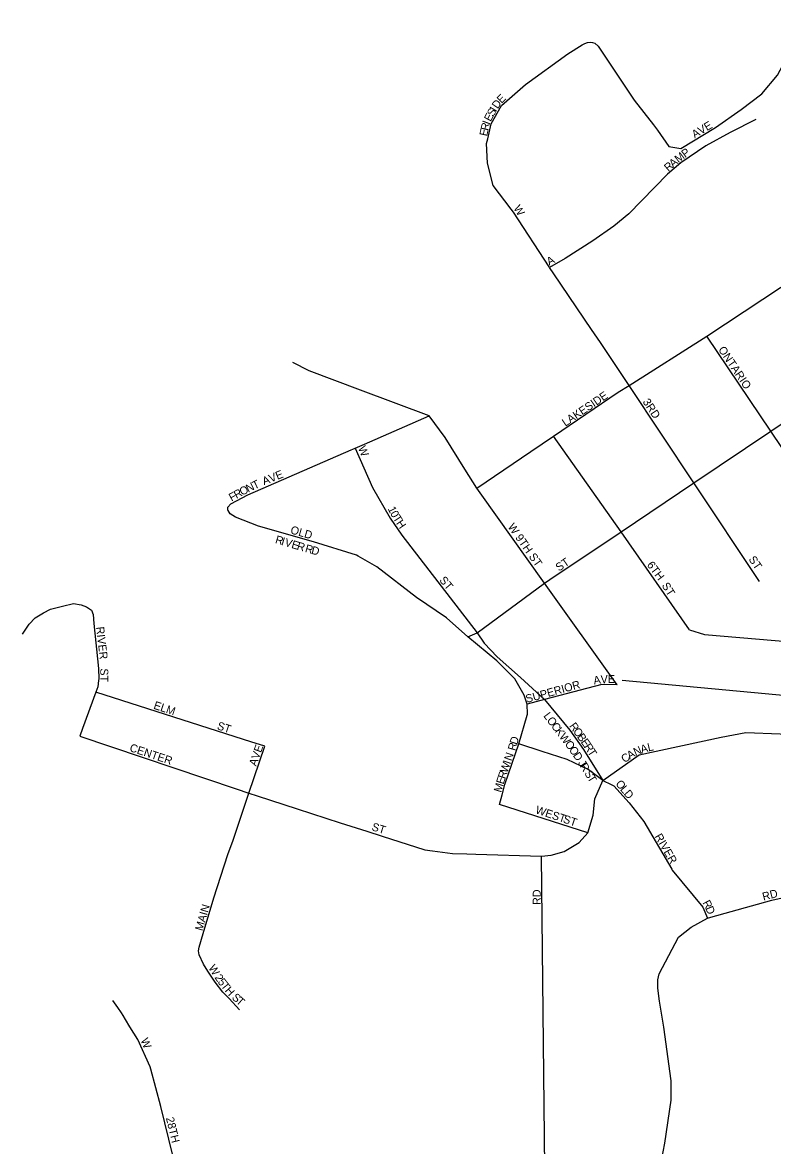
# Model space of a CAD drawing. Extents: x 0 to 96.2, y -27.5 to 31.3.
# Drawn here: x 3.858 to 4.744, y 18.275 to 19.6 of the extents above; entities that cross this region are included whole.
import ezdxf

# ---------------------------------------------------------------- set-up
doc = ezdxf.new("R2010")
doc.units = 0
doc.layers.add('TB_PP_20x10_GRID', color=7, linetype='Continuous')
doc.layers.add('TB_PP_30x10', color=7, linetype='Continuous')

msp = doc.modelspace()

# ---------------------------------------------------------------- linework, layer by layer
at = {"layer": 'TB_PP_20x10_GRID'}
for points in [[(4.608, 19.4727), (4.6213, 19.4537), (4.6356, 19.4511), (4.6765, 19.4758), (4.7067, 19.497), (4.7309, 19.5157), (4.7496, 19.5375), (4.7593, 19.5562), (4.7701, 19.5754), (4.784, 19.5861), (4.8006, 19.5998)], [(4.4076, 19.4626), (4.4118, 19.4803), (4.424, 19.5019), (4.4522, 19.5268), (4.5021, 19.5628), (4.5192, 19.5734), (4.5222, 19.5749), (4.5254, 19.5761), (4.5287, 19.5764), (4.5312, 19.5762), (4.5341, 19.5752), (4.5379, 19.572), (4.5802, 19.508), (4.6034, 19.4791), (4.608, 19.4727)], [(4.5743, 19.1717), (4.6662, 19.2297), (4.8411, 19.3455), (4.9286, 19.4096), (5.0545, 19.4913), (5.1255, 19.5402), (5.1289, 19.5424)], [(4.724, 19.4852), (4.6935, 19.4702), (4.6649, 19.4544), (4.6354, 19.4341), (4.6196, 19.4208), (4.574, 19.3741), (4.5563, 19.3596), (4.5317, 19.3424), (4.499, 19.3215), (4.4806, 19.3107)], [(4.4353, 19.3794), (4.414, 19.4077), (4.4074, 19.4337), (4.4063, 19.457), (4.4076, 19.4626)], [(4.4799, 19.3116), (4.4378, 19.3761), (4.4353, 19.3794)], [(4.5405, 19.2224), (4.5301, 19.2376), (4.4856, 19.3032), (4.4806, 19.3107), (4.4799, 19.3116)], [(4.4808, 18.9427), (4.565, 18.9991), (4.6509, 19.0567), (4.7418, 19.1176), (4.9176, 19.2354), (5.0055, 19.2943)], [(4.5743, 19.1717), (4.5405, 19.2224)], [(4.7433, 19.1154), (4.7418, 19.1176), (4.6662, 19.2297)], [(4.2576, 19.1662), (4.1968, 19.189), (4.1776, 19.1986)], [(4.4852, 19.1119), (4.5617, 19.1638), (4.5743, 19.1717)], [(4.7283, 18.9404), (4.6509, 19.0567), (4.5743, 19.1717)], [(4.3385, 19.136), (4.2576, 19.1662)], [(4.2483, 19.0965), (4.251, 19.0977), (4.2623, 19.1026), (4.3385, 19.136)], [(4.3987, 19.0449), (4.3948, 19.0505), (4.3806, 19.0729), (4.3572, 19.1101), (4.3385, 19.136)], [(4.8205, 19.001), (4.7894, 19.0472), (4.7433, 19.1154)], [(4.4586, 19.0938), (4.485, 19.1118), (4.4852, 19.1119)], [(4.6455, 18.8834), (4.565, 18.9991), (4.485, 19.1118)], [(4.1013, 19.024), (4.1009, 19.0246), (4.1009, 19.0264), (4.1009, 19.0283), (4.1045, 19.0319), (4.1244, 19.0427), (4.2465, 19.0957), (4.2483, 19.0965)], [(4.251, 19.0977), (4.2715, 19.0513), (4.2925, 19.0153), (4.3063, 18.9952), (4.3952, 18.8799)], [(4.3948, 19.0505), (4.4586, 19.0938)], [(4.5602, 18.8186), (4.4747, 18.9386), (4.3987, 19.0449)], [(4.3839, 18.8752), (4.3591, 18.8977), (4.3235, 18.9215), (4.2765, 18.9579), (4.2548, 18.9702), (4.2528, 18.9714), (4.2021, 18.9873), (4.1372, 19.0057), (4.1097, 19.0165), (4.1035, 19.0204), (4.1013, 19.024)], [(4.3839, 18.8752), (4.3952, 18.8799), (4.4747, 18.9386), (4.4808, 18.9427)], [(3.8584, 18.8784), (3.8663, 18.8901), (3.8736, 18.8974), (3.8832, 18.9033), (3.8914, 18.9079), (3.9056, 18.9113), (3.9058, 18.9114)], [(3.9058, 18.9114), (3.9188, 18.9146), (3.9278, 18.913), (3.9342, 18.9106), (3.9398, 18.9066), (3.942, 18.9016), (3.9426, 18.8907), (3.9481, 18.838), (3.9484, 18.8256), (3.9483, 18.8236)], [(4.3952, 18.8799), (4.4033, 18.8677), (4.4187, 18.8514), (4.4462, 18.8272), (4.4746, 18.8012), (4.5043, 18.765), (4.5207, 18.7424), (4.5436, 18.7057)], [(4.6455, 18.8834), (4.6634, 18.8781), (4.8069, 18.8658)], [(4.4542, 18.7829), (4.4546, 18.7841), (4.454, 18.7957), (4.4506, 18.8064), (4.4394, 18.8256), (4.4182, 18.8467), (4.3839, 18.8752)], [(3.9483, 18.8236), (3.9475, 18.816), (3.945, 18.8098), (3.9293, 18.7669)], [(4.5662, 18.8241), (4.9798, 18.7855), (5.0011, 18.7941)], [(4.5602, 18.8186), (4.5421, 18.819), (4.4746, 18.8012), (4.454, 18.7957)], [(4.1432, 18.7465), (4.1293, 18.7509), (3.945, 18.8098)], [(4.4246, 18.6887), (4.4279, 18.7009), (4.4282, 18.702), (4.4442, 18.7489), (4.4542, 18.7829)], [(3.9293, 18.7669), (3.9261, 18.7582), (4.1108, 18.6959), (4.1258, 18.6909), (4.1356, 18.6877)], [(4.5436, 18.7057), (4.5862, 18.7359), (4.6832, 18.7567), (4.7123, 18.7622), (4.7525, 18.7608), (4.941, 18.747), (5.0005, 18.74), (5.0233, 18.7344), (5.0355, 18.7177), (5.0687, 18.677), (5.0723, 18.6657), (5.0784, 18.6246), (5.0504, 18.5737), (5.0615, 18.5459), (5.0812, 18.5098), (5.1031, 18.4683), (5.1509, 18.4047), (5.2415, 18.2842)], [(4.1258, 18.6909), (4.1444, 18.7461), (4.1432, 18.7465)], [(4.5436, 18.7057), (4.5261, 18.7186), (4.5013, 18.7303), (4.4719, 18.7399), (4.4442, 18.7489)], [(4.383, 18.6191), (4.3935, 18.6189), (4.4712, 18.6163), (4.4824, 18.6175), (4.4978, 18.6218), (4.5153, 18.6324), (4.5256, 18.6441), (4.532, 18.6648), (4.5339, 18.6839), (4.5436, 18.7057), (4.5532, 18.7011)], [(4.0716, 18.5254), (4.0844, 18.5675), (4.101, 18.6183), (4.1071, 18.6353), (4.1258, 18.6909)], [(4.5532, 18.7011), (4.5565, 18.6995), (4.5745, 18.6792), (4.5917, 18.6573), (4.6247, 18.6012)], [(4.1356, 18.6877), (4.1825, 18.6722), (4.2336, 18.6558)], [(4.5256, 18.6441), (4.4216, 18.6776), (4.4246, 18.6887)], [(4.2336, 18.6558), (4.265, 18.6458), (4.2828, 18.6401)], [(4.2828, 18.6401), (4.3332, 18.6241), (4.3424, 18.6228), (4.3661, 18.6195), (4.383, 18.6191)], [(4.475, 18.2488), (4.4712, 18.6163)], [(4.6247, 18.6012), (4.6254, 18.5999), (4.6615, 18.5562), (4.6668, 18.5433)], [(4.6708, 18.5444), (4.7429, 18.5647), (4.7832, 18.5736), (4.8087, 18.581), (4.8259, 18.5842), (4.8392, 18.588)], [(4.4759, 18.1559), (4.4822, 18.1567), (4.5061, 18.1662), (4.5322, 18.1783), (4.5517, 18.1892), (4.5765, 18.2073), (4.5958, 18.2245), (4.6062, 18.2401), (4.6127, 18.2577), (4.6167, 18.2779), (4.6241, 18.3288), (4.6239, 18.3513), (4.6153, 18.4149), (4.6104, 18.4453), (4.6083, 18.4608), (4.6082, 18.4706), (4.6097, 18.4777), (4.6328, 18.521), (4.6477, 18.5326), (4.6668, 18.5433), (4.6708, 18.5444)], [(4.1148, 18.4353), (4.1026, 18.4484), (4.0948, 18.4562), (4.086, 18.4679), (4.0774, 18.4809), (4.072, 18.4889), (4.067, 18.5), (4.0664, 18.5048), (4.067, 18.5093), (4.0716, 18.5254)], [(3.9754, 18.4315), (3.9709, 18.4381), (3.9652, 18.4463)], [(4.0099, 18.3654), (4.0092, 18.3678), (3.9946, 18.4004), (3.9851, 18.4153), (3.9802, 18.4237), (3.9772, 18.4286), (3.9754, 18.4315)], [(4.0593, 18.1591), (4.0407, 18.2443), (4.0216, 18.3212), (4.0099, 18.3654)]]:
    msp.add_lwpolyline(points, dxfattribs=at)

# ---------------------------------------------------------------- texts
at = {"layer": 'TB_PP_30x10'}
for s, rotation, p in [('E', 44.6137, (4.4238, 19.5037)), ('I', 59.7561, (4.4174, 19.4937)), ('D', 55.819, (4.4194, 19.4972)), ('E', 62.3229, (4.411, 19.4822)), ('S', 59.7672, (4.4141, 19.488)), ('E', 77.7793, (4.4068, 19.4651)), ('R', 77.2657, (4.4082, 19.4716)), ('I', 69.7816, (4.4097, 19.4786)), ('AVE', 30.965, (4.6518, 19.4629)), ('M', 37.8207, (4.6326, 19.4337)), ('P', 36.3126, (4.6405, 19.4398)), ('R', 40.8067, (4.6207, 19.4234)), ('A', 40.8076, (4.6264, 19.4283)), ('W', 302.4763, (4.4375, 19.3807)), ('A', 29.0443, (4.4802, 19.3128)), ('ONTARIO', 303.9425, (4.6792, 19.214)), ('LAKESIDE', 34.1585, (4.4992, 19.1228)), ('3RD', 303.6901, (4.59, 19.1524)), ('W', 292.6069, (4.2543, 19.0979)), ('AVE', 22.162, (4.1437, 19.0539)), ('R', 28.5639, (4.111, 19.0378)), ('O', 27.7382, (4.1176, 19.0414)), ('N', 25.7048, (4.1249, 19.0452)), ('T', 25.3553, (4.1324, 19.0488)), ('F', 28.569, (4.1052, 19.0346)), ('1', 296.7606, (4.2893, 19.0263)), ('0', 298.8406, (4.2921, 19.0208)), ('T', 302.8211, (4.2953, 19.0151)), ('H', 304.2578, (4.299, 19.0092)), ('W 9TH ST', 305.2157, (4.4308, 19.0049)), ('OLD', 344.0556, (4.174, 18.9973)), ('R', 343.3008, (4.1561, 18.986)), ('I', 343.2798, (4.1632, 18.9838)), ('V', 343.3006, (4.1672, 18.9826)), ('E', 343.2929, (4.1752, 18.9802)), ('R', 343.413, (4.1816, 18.9783)), ('R', 344.0285, (4.1913, 18.9754)), ('D', 345.2432, (4.1987, 18.9733)), ('ST', 304.6908, (4.715, 18.9666)), ('ST', 34.7021, (4.4917, 18.952)), ('6TH', 306.8751, (4.5949, 18.9599)), ('ST', 309.8092, (4.3499, 18.9417)), ('ST', 302.7431, (4.6125, 18.9357)), ('RIVER', 276.7905, (3.9453, 18.8866)), ('ST', 270, (3.9503, 18.838)), ('A', 9.6851, (4.5331, 18.8189)), ('V', 2.3614, (4.541, 18.8203)), ('E', 0.0546, (4.5492, 18.8207)), ('SUPERIOR', 15.477, (4.4538, 18.7972)), ('ELM', 341.5675, (4.0124, 18.7906)), ('L', 307.1705, (4.4728, 18.7818)), ('ST', 341.5607, (4.0874, 18.7664)), ('O', 307.1869, (4.4768, 18.7765)), ('C', 307.1941, (4.4819, 18.7698)), ('R', 305.6845, (4.5033, 18.7699)), ('D', 72.4843, (4.4421, 18.7473)), ('K', 307.1847, (4.4864, 18.7638)), ('W', 307.1958, (4.4914, 18.7572)), ('O', 305.6723, (4.5077, 18.7638)), ('B', 305.6788, (4.5125, 18.7571)), ('CENTER', 341.5625, (3.9841, 18.7406)), ('AVE', 70.3422, (4.1343, 18.722)), ('R', 74.4616, (4.4401, 18.7402)), ('O', 306.7825, (4.498, 18.7486)), ('O', 305.497, (4.5029, 18.742)), ('E', 305.6076, (4.5169, 18.751)), ('R', 303.9932, (4.5207, 18.7456)), ('T', 302.796, (4.5249, 18.7394)), ('N', 23.5469, (4.582, 18.7344)), ('A', 16.3872, (4.5893, 18.7376)), ('L', 12.8073, (4.5972, 18.7399)), ('N', 71.1504, (4.4355, 18.7282)), ('D', 304.1145, (4.5077, 18.7352)), ('C', 34.2866, (4.569, 18.7261)), ('A', 30.7067, (4.5751, 18.7303)), ('W', 71.1503, (4.4306, 18.714)), ('I', 71.1588, (4.4342, 18.7242)), ('J', 302.3807, (4.5137, 18.7263)), ('R', 301.9385, (4.5159, 18.7228)), ('S', 301.7549, (4.5212, 18.7143)), ('E', 72.3167, (4.4262, 18.7006)), ('R', 71.2118, (4.4282, 18.7069)), ('T', 301.7549, (4.5247, 18.7086)), ('O', 308.4175, (4.5579, 18.7017)), ('M', 73.8695, (4.4235, 18.691)), ('L', 310.5727, (4.5633, 18.6949)), ('D', 310.6197, (4.5676, 18.6898)), ('WEST', 341.5632, (4.4632, 18.6672)), ('ST', 341.5651, (4.4957, 18.6564)), ('ST', 342.6452, (4.2699, 18.6472)), ('RIVER', 300.0203, (4.6042, 18.6398)), ('RD', 90, (4.4701, 18.5589)), ('RD', 14.7447, (4.733, 18.5639)), ('MAIN', 74.0513, (4.071, 18.5277)), ('R', 297.5968, (4.6608, 18.5616)), ('D', 293.3077, (4.6642, 18.5551)), ('W', 302.3564, (4.0775, 18.4848)), ('2', 304.1604, (4.0848, 18.4733)), ('5', 307.1143, (4.0884, 18.468)), ('T', 308.6666, (4.0921, 18.4632)), ('H', 312.0853, (4.0967, 18.4575)), ('S', 318.3444, (4.1048, 18.4487)), ('T', 318.9818, (4.1099, 18.4442)), ('W', 292.6225, (3.9977, 18.3996)), ('28TH', 283.7097, (4.0277, 18.3076))]:
    msp.add_text(s, height=0.00947, rotation=rotation, dxfattribs=at).set_placement(p)

doc.saveas('drawing.dxf')
